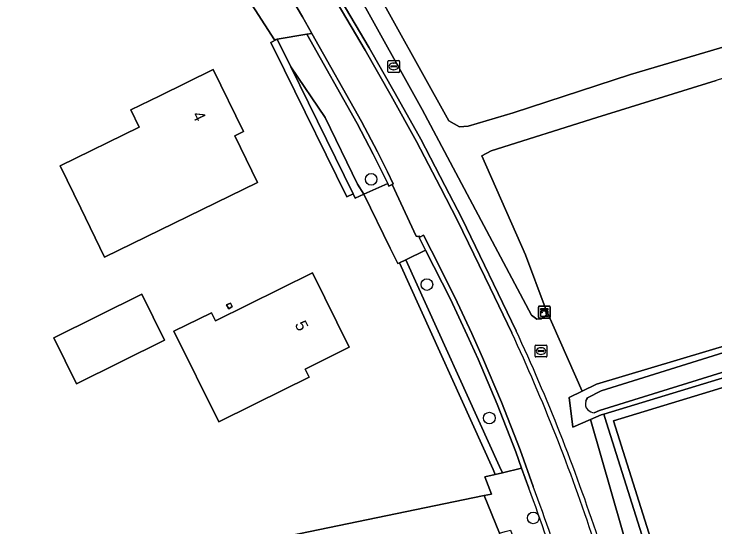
# Model space of a CAD drawing. Extents: x 162510 to 163918, y 388494 to 389774.
# Drawn here: x 163079.2 to 163138.2, y 389644.2 to 389687.4 of the extents above; entities that cross this region are included whole.
import ezdxf

# ---------------------------------------------------------------- set-up
doc = ezdxf.new("R2010")
doc.units = 0
for name, color, linetype in [('IMGEO_Boom', 7, 'Continuous'), ('IMGEO_Erf', 7, 'Continuous'), ('IMGEO_Grasland_agrarisch', 7, 'Continuous'), ('IMGEO_Grasland_overig', 7, 'Continuous'), ('IMGEO_Groenvoorziening', 7, 'Continuous'), ('IMGEO_Haag', 7, 'Continuous'), ('IMGEO_Kast', 7, 'Continuous'), ('IMGEO_Loofbos', 7, 'Continuous'), ('IMGEO_Oever', 7, 'Continuous'), ('IMGEO_Pand', 7, 'Continuous'), ('IMGEO_Pand_nummerreeks', 7, 'Continuous'), ('IMGEO_Rijbaan_lokaal_gesloten', 7, 'Continuous'), ('IMGEO_Rijbaan_lokaal_halfverhard', 7, 'Continuous'), ('IMGEO_Rijbaan_lokaal_open', 7, 'Continuous'), ('IMGEO_Rioolput', 7, 'Continuous'), ('IMGEO_Sloot', 7, 'Continuous'), ('IMGEO_Waterloop', 7, 'Continuous')]:
    doc.layers.add(name, color=color, linetype=linetype)

msp = doc.modelspace()

# ---------------------------------------------------------------- linework, layer by layer
at = {"layer": 'IMGEO_Boom'}
for centre in [(163109.294, 389673.454), (163113.984, 389664.609), (163119.239, 389653.384), (163122.93, 389644.985)]:
    msp.add_circle(centre, 0.489, dxfattribs=at)
at = {"layer": 'IMGEO_Erf'}
for points in [[(163049.049, 389695.765), (163063.359, 389648.597), (163066.29, 389636.03), (163118.807, 389646.87), (163119.432, 389646.987), (163118.856, 389648.436), (163119.742, 389648.645), (163119.558, 389649.049), (163111.68, 389666.434), (163111.535, 389666.363), (163110.904, 389667.657), (163108.673, 389672.194), (163107.961, 389671.869), (163107.786, 389672.225), (163107.244, 389671.968), (163101.992, 389682.639), (163100.849, 389684.96), (163101.387, 389685.225), (163101.171, 389685.168), (163098.727, 389688.984)], [(163182.625, 389669.258), (163129.682, 389653.16), (163134.78, 389636.977), (163137.227, 389629.159), (163136.654, 389628.98), (163134.208, 389636.797), (163129.108, 389652.985), (163128.88, 389653.708), (163128.66, 389653.641), (163127.749, 389653.248), (163135.626, 389625.828), (163137.442, 389617.529), (163137.903, 389615.424), (163141.862, 389590.82)]]:
    msp.add_lwpolyline(points, dxfattribs=at)
for points in [[(163105.431, 389678.646), (163102.53, 389682.904), (163107.786, 389672.225), (163107.961, 389671.869), (163108.673, 389672.194), (163108.152, 389673.033)], [(163086.865, 389666.921), (163084.863, 389671.027), (163083.127, 389674.587), (163089.778, 389677.83), (163089.067, 389679.286), (163091.52, 389680.482), (163096.014, 389682.674), (163098.548, 389677.48), (163097.811, 389677.121), (163099.726, 389673.196)], [(163107.455, 389659.339), (163103.754, 389657.49), (163104.067, 389656.819), (163099.586, 389654.602), (163099.363, 389654.492), (163096.466, 389653.052), (163092.704, 389660.689), (163095.856, 389662.235), (163096.196, 389661.565), (163104.351, 389665.606)], [(163091.918, 389659.936), (163084.499, 389656.262), (163082.588, 389660.114), (163090.012, 389663.797)], [(163097.328, 389662.556), (163097.127, 389662.909), (163097.452, 389663.032), (163097.596, 389662.754)]]:
    msp.add_lwpolyline(points, close=True, dxfattribs=at)
at = {"layer": 'IMGEO_Grasland_agrarisch'}
for points in [[(163130.743, 389593.913), (163130.817, 389595.747), (163129.494, 389604.011), (163127.314, 389615.888), (163124.168, 389630.542), (163122.348, 389637.109), (163120.085, 389643.716), (163118.807, 389646.87), (163066.29, 389636.03), (163063.359, 389648.597), (163049.049, 389695.765), (163050.188, 389696.144), (163051.311, 389696.499), (163053.349, 389697.161), (163060.778, 389699.572), (163079.145, 389705.133), (163083.993, 389706.601), (163041.935, 389748.28), (163000, 389735.447)], [(163221.117, 389707.006), (163174.851, 389693.27), (163153.598, 389686.6), (163145.338, 389683.966), (163138.314, 389681.76), (163128.287, 389678.659), (163119.39, 389675.843), (163118.596, 389675.44), (163122.278, 389667.104), (163123.947, 389662.664), (163127.06, 389655.645), (163128.253, 389656.225), (163164.76, 389667.142), (163184.977, 389672.998), (163185.275, 389671.675), (163192.889, 389673.852), (163192.775, 389674.365), (163208.184, 389679.306)]]:
    msp.add_lwpolyline(points, dxfattribs=at)
at = {"layer": 'IMGEO_Grasland_overig'}
for points in [[(163105.958, 389689.895), (163109.125, 389684.514), (163111.316, 389680.672), (163113.471, 389676.828), (163115.487, 389672.948), (163116.916, 389670.179), (163121.488, 389660.72)], [(163135.234, 389619.13), (163135.44, 389618.079), (163135.597, 389617.199), (163137.442, 389617.529), (163135.626, 389625.828), (163127.749, 389653.248), (163126.259, 389652.605), (163125.951, 389655.106), (163127.06, 389655.645), (163123.947, 389662.664), (163124.043, 389662.028), (163123.608, 389661.72), (163123.227, 389661.705), (163122.798, 389662.039), (163113.581, 389679.311), (163108.132, 389689.136)], [(163121.955, 389649.167), (163120.337, 389648.785), (163119.742, 389648.645), (163118.856, 389648.436), (163119.432, 389646.987), (163118.807, 389646.87), (163120.085, 389643.716), (163120.563, 389643.837), (163121.03, 389643.956), (163122.598, 389639.595), (163123.905, 389635.216), (163125.403, 389629.439), (163129.208, 389611.859), (163131.988, 389595.99), (163132.038, 389595.088)], [(163122.558, 389647.478), (163121.955, 389649.167)]]:
    msp.add_lwpolyline(points, dxfattribs=at)
msp.add_lwpolyline([(163103.877, 389685.645), (163101.387, 389685.225), (163102.53, 389682.904), (163105.431, 389678.646), (163108.152, 389673.033), (163108.673, 389672.194), (163110.684, 389673.112), (163110.309, 389673.899), (163109.47, 389675.576), (163108.119, 389678.134)], close=True, dxfattribs=at)
for centre, radius, start, end in [((162975.888, 389593.026), 160.568, 18.22911, 24.93527), ((162972.42, 389591.396), 160.27, 17.28782, 20.48244)]:
    msp.add_arc(centre, radius, start, end, dxfattribs=at)
at = {"layer": 'IMGEO_Groenvoorziening'}
for points in [[(163102.53, 389682.904), (163101.387, 389685.225), (163100.849, 389684.96), (163101.992, 389682.639), (163107.244, 389671.968), (163107.786, 389672.225)], [(163182.625, 389669.258), (163189.08, 389648.043), (163197.592, 389622.245), (163198.162, 389622.433), (163189.652, 389648.224), (163182.976, 389670.167), (163128.88, 389653.708), (163129.108, 389652.985), (163134.208, 389636.797), (163136.654, 389628.98), (163137.227, 389629.159), (163134.78, 389636.977), (163129.682, 389653.16)], [(163113.87, 389667.508), (163112.219, 389666.698), (163120.105, 389649.297), (163120.337, 389648.785), (163121.955, 389649.167), (163121.459, 389650.556), (163119.9, 389654.563), (163118.286, 389658.324), (163117.386, 389660.342), (163115.969, 389663.383)], [(163112.219, 389666.698), (163111.68, 389666.434), (163119.558, 389649.049), (163119.742, 389648.645), (163120.337, 389648.785), (163120.105, 389649.297)]]:
    msp.add_lwpolyline(points, close=True, dxfattribs=at)
at = {"layer": 'IMGEO_Haag'}
for points in [[(163101.387, 389685.225), (163100.849, 389684.96), (163101.992, 389682.639), (163107.244, 389671.968), (163107.786, 389672.225), (163102.53, 389682.904)], [(163182.625, 389669.258), (163189.08, 389648.043), (163197.592, 389622.245), (163198.162, 389622.433), (163189.652, 389648.224), (163182.976, 389670.167), (163128.88, 389653.708), (163129.108, 389652.985), (163134.208, 389636.797), (163136.654, 389628.98), (163137.227, 389629.159), (163134.78, 389636.977), (163129.682, 389653.16)], [(163112.219, 389666.698), (163111.68, 389666.434), (163119.558, 389649.049), (163119.742, 389648.645), (163120.337, 389648.785), (163120.105, 389649.297)]]:
    msp.add_lwpolyline(points, close=True, dxfattribs=at)
at = {"layer": 'IMGEO_Kast'}
for p, q in [((163123.368, 389661.865), (163123.368, 389662.706)), ((163123.368, 389662.706), (163123.368, 389661.865)), ((163123.443, 389662.79), (163124.284, 389662.79)), ((163124.284, 389662.79), (163123.443, 389662.79)), ((163124.368, 389662.715), (163124.368, 389661.874)), ((163124.368, 389661.874), (163124.368, 389662.715)), ((163124.293, 389661.79), (163123.452, 389661.79)), ((163123.452, 389661.79), (163124.293, 389661.79))]:
    msp.add_line(p, q, dxfattribs=at)
for points in [[(163123.563, 389662.58), (163124.163, 389662.58), (163124.163, 389662.495), (163123.563, 389662.495), (163123.563, 389662.58)], [(163123.563, 389662.405), (163124.163, 389662.405), (163124.163, 389661.916), (163123.563, 389661.916), (163123.563, 389662.405)]]:
    msp.add_lwpolyline(points, dxfattribs=at)
msp.add_circle((163123.647, 389662.254), 0.0377, dxfattribs=at)
for centre, start, end in [((163123.446, 389662.712), 92.4484, 184.28452), ((163123.446, 389662.712), 92.4484, 184.28452), ((163124.29, 389662.712), 2.4484, 94.28452), ((163124.29, 389662.712), 2.4484, 94.28452), ((163123.446, 389661.868), 182.4484, 274.28452), ((163123.446, 389661.868), 182.4484, 274.28452), ((163124.29, 389661.868), 272.4484, 4.28452), ((163124.29, 389661.868), 272.4484, 4.28452)]:
    msp.add_arc(centre, 0.0779, start, end, dxfattribs=at)
at = {"layer": 'IMGEO_Loofbos'}
msp.add_lwpolyline([(163146.108, 389725.524), (163135.483, 389722.832), (163127.609, 389720.051), (163103.914, 389711.813), (163098.607, 389709.594), (163103.731, 389699.687), (163104.676, 389697.495), (163105.154, 389696.932), (163105.373, 389696.135), (163105.091, 389695.608), (163108.099, 389691.141), (163108.226, 389691.191), (163108.909, 389690.83), (163115.833, 389678.377), (163116.717, 389677.861), (163117.454, 389677.931), (163121.248, 389679.04), (163131.106, 389682.278), (163161.637, 389691.325)], dxfattribs=at)
at = {"layer": 'IMGEO_Oever'}
for points in [[(163204.587, 389611.791), (163198.781, 389628.315), (163185.703, 389669.774), (163185.275, 389671.675), (163184.977, 389672.998), (163164.76, 389667.142), (163128.253, 389656.225), (163127.06, 389655.645), (163125.951, 389655.106), (163126.259, 389652.605), (163127.749, 389653.248), (163128.66, 389653.641), (163128.88, 389653.708), (163182.976, 389670.167), (163183.199, 389670.235), (163185.361, 389663.193), (163202.535, 389611.212)], [(163127.357, 389654.808), (163127.418, 389654.953), (163127.49, 389655.096), (163128.648, 389655.683), (163141.202, 389659.581), (163157.512, 389664.501), (163184.715, 389672.63), (163185.175, 389670.122), (163186.363, 389666.106), (163190.931, 389652.108), (163195.699, 389637.165), (163203.774, 389611.714), (163205.313, 389601.982), (163207.459, 389588.089), (163208.421, 389584.173), (163209.288, 389580.644), (163210.375, 389576.218), (163210.345, 389576.081), (163210.307, 389575.951)], [(163189.571, 389651.666), (163183.371, 389670.684), (163157.956, 389663.025), (163141.699, 389658.118), (163128.509, 389654.004), (163128.064, 389653.812)]]:
    msp.add_lwpolyline(points, dxfattribs=at)
for centre, radius, start, end in [((163128.006, 389654.569), 0.691, 159.77716, 224.54203), ((163128.268, 389654.92), 1.127, 227.90293, 259.55077)]:
    msp.add_arc(centre, radius, start, end, dxfattribs=at)
at = {"layer": 'IMGEO_Pand'}
for points in [[(163098.548, 389677.48), (163096.014, 389682.674), (163091.52, 389680.482), (163089.067, 389679.286), (163089.778, 389677.83), (163083.127, 389674.587), (163084.863, 389671.027), (163086.865, 389666.921), (163099.726, 389673.196), (163097.811, 389677.121)], [(163092.704, 389660.689), (163096.466, 389653.052), (163099.363, 389654.492), (163099.586, 389654.602), (163104.067, 389656.819), (163103.754, 389657.49), (163107.455, 389659.339), (163104.351, 389665.606), (163096.196, 389661.565), (163095.856, 389662.235)], [(163091.918, 389659.936), (163090.012, 389663.797), (163082.588, 389660.114), (163084.499, 389656.262)], [(163097.328, 389662.556), (163097.596, 389662.754), (163097.452, 389663.032), (163097.127, 389662.909)]]:
    msp.add_lwpolyline(points, close=True, dxfattribs=at)
at = {"layer": 'IMGEO_Rijbaan_lokaal_gesloten'}
for points in [[(163121.127, 389660.548), (163119.315, 389664.342), (163116.561, 389669.996), (163115.132, 389672.764), (163113.122, 389676.632), (163110.969, 389680.474), (163108.78, 389684.311), (163105.613, 389689.692), (163102.221, 389695.466)], [(163102.249, 389689.268), (163103.522, 389687.12), (163104.281, 389685.761), (163104.306, 389685.717), (163108.469, 389678.328), (163109.828, 389675.755), (163110.67, 389674.071), (163111.15, 389673.064), (163111.057, 389673.019), (163113.094, 389668.686), (163113.228, 389668.645), (163113.322, 389668.688), (163113.382, 389668.604), (163113.686, 389668.751), (163114.366, 389667.446), (163116.332, 389663.552), (163117.751, 389660.505), (163118.654, 389658.482), (163120.273, 389654.708), (163121.832, 389650.701), (163122.933, 389647.618)]]:
    msp.add_lwpolyline(points, dxfattribs=at)
for centre, radius, start, end in [((162975.939, 389593.05), 160.111, 18.22398, 24.93371), ((162971.596, 389591.123), 161.538, 17.29309, 20.47081)]:
    msp.add_arc(centre, radius, start, end, dxfattribs=at)
at = {"layer": 'IMGEO_Rijbaan_lokaal_halfverhard'}
for points in [[(163102.221, 389695.466), (163105.613, 389689.692), (163108.78, 389684.311), (163110.969, 389680.474), (163113.122, 389676.632), (163115.132, 389672.764), (163116.561, 389669.996), (163119.315, 389664.342), (163121.127, 389660.548)], [(163121.488, 389660.72), (163116.916, 389670.179), (163115.487, 389672.948), (163113.471, 389676.828), (163111.316, 389680.672), (163109.125, 389684.514), (163105.958, 389689.895)], [(163113.382, 389668.604), (163113.326, 389668.576), (163113.87, 389667.508), (163115.969, 389663.383), (163117.386, 389660.342), (163118.286, 389658.324), (163119.9, 389654.563), (163121.459, 389650.556), (163121.955, 389649.167), (163122.558, 389647.478)], [(163122.933, 389647.618), (163121.832, 389650.701), (163120.273, 389654.708), (163118.654, 389658.482), (163117.751, 389660.505), (163116.332, 389663.552), (163114.366, 389667.446), (163113.686, 389668.751), (163113.382, 389668.604)]]:
    msp.add_lwpolyline(points, dxfattribs=at)
msp.add_lwpolyline([(163104.306, 389685.717), (163103.877, 389685.645), (163108.119, 389678.134), (163109.47, 389675.576), (163110.309, 389673.899), (163110.684, 389673.112), (163110.789, 389672.892), (163111.057, 389673.019), (163111.15, 389673.064), (163110.67, 389674.071), (163109.828, 389675.755), (163108.469, 389678.328)], close=True, dxfattribs=at)
for centre, radius, start, end in [((162975.939, 389593.05), 160.111, 18.22398, 24.93371), ((162975.888, 389593.026), 160.568, 18.22911, 24.93527), ((162972.42, 389591.396), 160.27, 17.28782, 20.48244), ((162971.596, 389591.123), 161.538, 17.29309, 20.47081)]:
    msp.add_arc(centre, radius, start, end, dxfattribs=at)
at = {"layer": 'IMGEO_Rijbaan_lokaal_open'}
for points in [[(163101.047, 389691.352), (163100.831, 389691.132), (163098.727, 389688.984), (163101.171, 389685.168), (163101.387, 389685.225), (163103.877, 389685.645), (163104.306, 389685.717), (163104.281, 389685.761), (163103.522, 389687.12), (163102.249, 389689.268), (163101.123, 389691.213)], [(163111.057, 389673.019), (163110.789, 389672.892), (163110.684, 389673.112), (163108.673, 389672.194), (163110.904, 389667.657), (163111.535, 389666.363), (163111.68, 389666.434), (163112.219, 389666.698), (163113.87, 389667.508), (163113.326, 389668.576), (163113.382, 389668.604), (163113.322, 389668.688), (163113.228, 389668.645), (163113.094, 389668.686)]]:
    msp.add_lwpolyline(points, close=True, dxfattribs=at)
at = {"layer": 'IMGEO_Rioolput'}
for p, q in [((163110.69, 389682.519), (163110.69, 389683.371)), ((163110.765, 389683.445), (163111.617, 389683.445)), ((163111.691, 389683.371), (163111.691, 389682.519)), ((163110.949, 389682.939), (163110.949, 389682.951)), ((163111.387, 389682.902), (163110.989, 389682.902)), ((163110.992, 389682.988), (163111.39, 389682.988)), ((163111.178, 389683.225), (163111.203, 389683.225)), ((163111.433, 389682.951), (163111.433, 389682.939)), ((163111.617, 389682.445), (163110.765, 389682.445)), ((163111.201, 389682.665), (163111.176, 389682.665)), ((163123.084, 389658.591), (163123.084, 389659.443)), ((163123.159, 389659.517), (163124.011, 389659.517)), ((163123.572, 389659.297), (163123.597, 389659.297)), ((163124.085, 389659.443), (163124.085, 389658.591)), ((163123.343, 389659.011), (163123.343, 389659.023)), ((163123.781, 389658.974), (163123.383, 389658.974)), ((163123.386, 389659.06), (163123.784, 389659.06)), ((163123.595, 389658.737), (163123.57, 389658.737)), ((163123.827, 389659.023), (163123.827, 389659.011)), ((163124.011, 389658.517), (163123.159, 389658.517))]:
    msp.add_line(p, q, dxfattribs=at)
for points in [[(163110.69, 389682.519), (163110.69, 389683.371)], [(163110.765, 389683.445), (163111.617, 389683.445)], [(163111.691, 389683.371), (163111.691, 389682.519)], [(163111.617, 389682.445), (163110.765, 389682.445)], [(163123.084, 389658.591), (163123.084, 389659.443)], [(163123.159, 389659.517), (163124.011, 389659.517)], [(163124.085, 389659.443), (163124.085, 389658.591)], [(163124.011, 389658.517), (163123.159, 389658.517)]]:
    msp.add_lwpolyline(points, dxfattribs=at)
for centre, radius, start, end in [((163110.767, 389683.369), 0.0765, 91.55205, 178.44795), ((163110.767, 389683.369), 0.0765, 91.55205, 178.44795), ((163111.615, 389683.369), 0.0765, 1.55205, 88.44795), ((163111.615, 389683.369), 0.0765, 1.55205, 88.44795), ((163110.989, 389682.948), 0.0403, 85.87752, 175.75265), ((163110.986, 389682.938), 0.0366, 178.93798, 274.71019), ((163111.39, 389682.945), 0.043, 264.86636, 352.45326), ((163111.394, 389682.95), 0.0386, 1.73085, 96.63898), ((163110.767, 389682.521), 0.0765, 181.55205, 268.44795), ((163110.767, 389682.521), 0.0765, 181.55205, 268.44795), ((163111.615, 389682.521), 0.0765, 271.55205, 358.44795), ((163111.615, 389682.521), 0.0765, 271.55205, 358.44795), ((163123.161, 389659.441), 0.0765, 91.55205, 178.44795), ((163123.161, 389659.441), 0.0765, 91.55205, 178.44795), ((163124.009, 389659.441), 0.0765, 1.55205, 88.44795), ((163124.009, 389659.441), 0.0765, 1.55205, 88.44795), ((163123.161, 389658.593), 0.0765, 181.55205, 268.44795), ((163123.161, 389658.593), 0.0765, 181.55205, 268.44795), ((163123.383, 389659.02), 0.0403, 85.87752, 175.75265), ((163123.38, 389659.01), 0.0366, 178.93798, 274.71019), ((163123.784, 389659.017), 0.043, 264.86636, 352.45326), ((163123.788, 389659.022), 0.0386, 1.73085, 96.63898), ((163124.009, 389658.593), 0.0765, 271.55205, 358.44795), ((163124.009, 389658.593), 0.0765, 271.55205, 358.44795)]:
    msp.add_arc(centre, radius, start, end, dxfattribs=at)
for centre, major_axis, ratio, start_param, end_param in [((163111.177, 389682.945), (-0.387, 0.002), 0.722429, 4.712389, 7.853982), ((163111.202, 389682.945), (-0.39, 0.002), 0.717154, 1.570796, 4.712389), ((163123.571, 389659.017), (-0.387, 0.002), 0.722429, 4.712389, 7.853982), ((163123.596, 389659.017), (-0.39, 0.002), 0.717154, 1.570796, 4.712389)]:
    msp.add_ellipse(centre, major_axis=major_axis, ratio=ratio, start_param=start_param, end_param=end_param, dxfattribs=at)
at = {"layer": 'IMGEO_Sloot'}
msp.add_lwpolyline([(163161.637, 389691.325), (163131.106, 389682.278), (163121.248, 389679.04), (163117.454, 389677.931), (163116.717, 389677.861), (163115.833, 389678.377), (163108.909, 389690.83), (163108.226, 389691.191), (163108.099, 389691.141), (163107.869, 389691.017), (163107.76, 389690.155), (163108.132, 389689.136), (163113.581, 389679.311), (163122.798, 389662.039), (163123.227, 389661.705), (163123.608, 389661.72), (163124.043, 389662.028), (163123.947, 389662.664), (163122.278, 389667.104), (163118.596, 389675.44), (163119.39, 389675.843), (163128.287, 389678.659), (163138.314, 389681.76)], dxfattribs=at)
at = {"layer": 'IMGEO_Waterloop'}
for points in [[(163210.307, 389575.951), (163210.345, 389576.081), (163210.375, 389576.218), (163209.288, 389580.644), (163208.421, 389584.173), (163207.459, 389588.089), (163205.313, 389601.982), (163203.774, 389611.714), (163195.699, 389637.165), (163190.931, 389652.108), (163186.363, 389666.106), (163185.175, 389670.122), (163184.715, 389672.63), (163157.512, 389664.501), (163141.202, 389659.581), (163128.648, 389655.683), (163127.49, 389655.096), (163127.418, 389654.953), (163127.357, 389654.808)], [(163128.064, 389653.812), (163128.509, 389654.004), (163141.699, 389658.118), (163157.956, 389663.025), (163183.371, 389670.684), (163189.571, 389651.666), (163194.4, 389636.752), (163202.709, 389611.448), (163204.545, 389601.862), (163206.704, 389587.879)]]:
    msp.add_lwpolyline(points, dxfattribs=at)
for centre, radius, start, end in [((163128.006, 389654.569), 0.691, 159.77716, 224.54203), ((163128.268, 389654.92), 1.127, 227.90293, 259.55077)]:
    msp.add_arc(centre, radius, start, end, dxfattribs=at)

# ---------------------------------------------------------------- texts
at = {"layer": 'IMGEO_Pand_nummerreeks'}
for s, rotation, p in [('4', 296.00634, (163094.212, 389678.885)), ('5', 296.34888, (163102.841, 389661.263))]:
    msp.add_text(s, height=1, rotation=rotation, dxfattribs=at).set_placement(p)

doc.saveas('drawing.dxf')
